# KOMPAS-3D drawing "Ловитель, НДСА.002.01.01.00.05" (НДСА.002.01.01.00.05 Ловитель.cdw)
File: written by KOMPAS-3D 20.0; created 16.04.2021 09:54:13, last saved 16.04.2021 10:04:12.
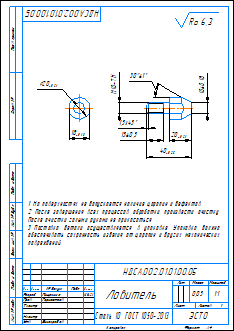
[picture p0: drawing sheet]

Sheet 1: A4, portrait

Document properties: Автор: 111; Параметр неуказанной шероховатости: Ra 6,3; PLM_CDWXDTO: <item xmlns="http://appius.ru/pdm" xmlns:xs="http://www.w3.org/2001/XMLSchema" xmlns:xsi="http://www.w3.org/2001/XMLSchema-instance" xsi:type="item">  <element xmlns:d2p1="http://v8.1c.ru/8.1/data/enterprise/current-config" xsi:type="d2p1:CatalogRef.aps_Элемен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; Масса: 0.05; Полное имя файла: НДСА.002.01.01.00.05 Ловитель.m3d

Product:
- Part/product: Ловитель  | designation НДСА.002.01.01.00.05
    Масса: 0.0514597
    additional columns: <item xmlns="http://appius.ru/pdm" xmlns:xs="http://www.w3.org/2001/XMLSchema" x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; <item xmlns="http://appius.ru/pdm" xmlns:xs="http://www.w3.org/2001/XMLSchema" x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
    source file: НДСА.002.01.01.00.05 Ловитель.cdw

Title block, sheet 1: Наименование: Ловитель; designation: НДСА.002.01.01.00.05; Материал: Сталь 10  ГОСТ 1050-2013; Масса: 0,05; Количество листов документа: 1; organisation: ЭСТО; Форматы листов документа: A4; stored path: C:\Users\s.pischagina\Desktop\PLM\НДСА.002.01.01.00.05 Ловитель.cdw; Разработал: Пищагина; Проверил: Горностаев; Утвердил: Виноградов; Разработал, date: 16.04.21

Views: Вид 1, Сверху, Проекционный вид 2
Referenced files in C:\Users\s.pischagina\Desktop\PLM\: НДСА.002.01.01.00.05 Ловитель.m3d
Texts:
  Ra 6,3
  НДСА.002.01.01.00.05 Ловитель
Dimensions and other numbers on the sheet: 18; 20; 10±0,18; 1,5; 15; 40; -7Н; 1:1; 1; 0,05; 16.04.21

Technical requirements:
  На поверхностях не допускается наличие царапин и дефектов.
  После завершения всех процессов обработки произвести очистку.
  После очистки голыми руками не прикасаться.
  Поставка детали осуществляется в упаковке. Упаковка должна
  обеспечивать сохранность изделия от царапин и других механических
  повреждений.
